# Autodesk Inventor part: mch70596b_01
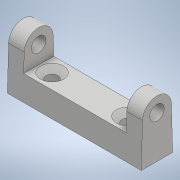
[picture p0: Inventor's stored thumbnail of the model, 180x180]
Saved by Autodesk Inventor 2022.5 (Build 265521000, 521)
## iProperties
Part Number: mch70596b_01
Material: 一般
Document SubType Name: Modeling
Designer: ImaoCorp
Density: 1 g/cm^3
Appearance: 既定
Author: ImaoCorp
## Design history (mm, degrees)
feature "mch70596b_01"
node "ソリッド1"
